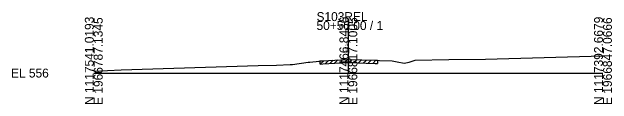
# Model space of a CAD drawing. Extents: x -26 to 163, y -10 to 24518.
# Drawn here: x -25.7 to 162.8, y 990.3 to 1019.2 of the extents above; entities that cross this region are included whole.
import ezdxf

# ---------------------------------------------------------------- set-up
doc = ezdxf.new("R2010")
doc.units = 0
for name, color, linetype in [('RD_GPK_XS_Cell', 7, 'Continuous'), ('RD_XS_ExGround', 7, 'Continuous'), ('RD_XS_ExPaveRet', 7, 'Continuous'), ('RD_XS_TX_Elev_EX', 7, 'Continuous')]:
    doc.layers.add(name, color=color, linetype=linetype)

msp = doc.modelspace()

# ---------------------------------------------------------------- linework, layer by layer
at = {"layer": 'RD_GPK_XS_Cell'}
for p, q in [((80, 1000), (80, 1016.31)), ((0, 1000), (80, 1000)), ((80, 1000), (160, 1000))]:
    msp.add_line(p, q, dxfattribs=at)
at = {"layer": 'RD_XS_ExGround'}
msp.add_lwpolyline([(0, 1000.65), (8.57, 1001.02), (51.69, 1002.41), (57.4, 1002.53), (61.75, 1002.68), (62.44, 1002.71), (67.33, 1003.39), (67.9, 1003.46), (70.83, 1003.78), (71.18, 1003.82), (71.97, 1003.86), (79.53, 1004.29), (80, 1004.27), (88.46, 1004.02), (89.18, 1004), (89.74, 1003.98), (93.78, 1003.81), (95.38, 1003.58), (97.5, 1003.15), (99.06, 1003.47), (101.01, 1004.05), (111.52, 1004.21), (123.13, 1004.38), (160, 1005.44)], dxfattribs=at)
at = {"layer": 'RD_XS_ExPaveRet'}
for p, q in [((71.18, 1002.82), (72.24, 1003.87)), ((71.18, 1002.82), (71.18, 1003.82)), ((71.97, 1002.86), (79.53, 1003.29)), ((72.68, 1002.9), (73.74, 1003.96)), ((74.18, 1002.98), (75.24, 1004.04)), ((75.68, 1003.07), (76.74, 1004.13)), ((77.18, 1003.15), (78.24, 1004.21)), ((78.68, 1003.24), (79.73, 1004.28)), ((79.53, 1003.29), (80, 1003.27)), ((80, 1003.27), (88.46, 1003.02)), ((80.18, 1003.27), (81.16, 1004.24)), ((81.68, 1003.22), (82.66, 1004.19)), ((83.18, 1003.18), (84.16, 1004.15)), ((84.68, 1003.13), (85.66, 1004.1)), ((86.18, 1003.09), (87.16, 1004.06)), ((87.68, 1003.04), (88.66, 1004.01)), ((88.46, 1003.02), (89.18, 1003)), ((89.18, 1004), (89.18, 1003)), ((71.18, 1002.82), (71.97, 1002.86))]:
    msp.add_line(p, q, dxfattribs=at)

# ---------------------------------------------------------------- texts
at = {"layer": 'RD_GPK_XS_Cell'}
for s, p in [('S103REL', (70, 1016.31)), ('50+50.00 / 1', (70, 1013.51)), ('EL 556', (-26, 998.6))]:
    msp.add_text(s, height=2.8, dxfattribs=at).set_placement(p)
for s, p in [('N 1117541.0193', (0, 990)), ('E 1966787.1345', (2.8, 990)), ('N 1117466.8436', (80, 990)), ('E 1966817.1005', (82.8, 990)), ('N 1117392.6679', (160, 990)), ('E 1966847.0666', (162.8, 990))]:
    msp.add_text(s, height=2.8, rotation=90, dxfattribs=at).set_placement(p)
at = {"layer": 'RD_XS_TX_Elev_EX'}
msp.add_text('560.27', height=0.8, rotation=90, dxfattribs=at).set_placement((79.9, 1006.27))

doc.saveas('drawing.dxf')
